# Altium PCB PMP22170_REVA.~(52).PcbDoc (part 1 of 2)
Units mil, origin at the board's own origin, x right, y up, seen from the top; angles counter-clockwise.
Board outline 4950 x 3450 mil, 2 copper layers (Top Layer, Bottom Layer), stack 62 mil thick; 75 components, 28 nets, 160 pads, 117 vias.
Unrouted connection lines stored in the file: 141.
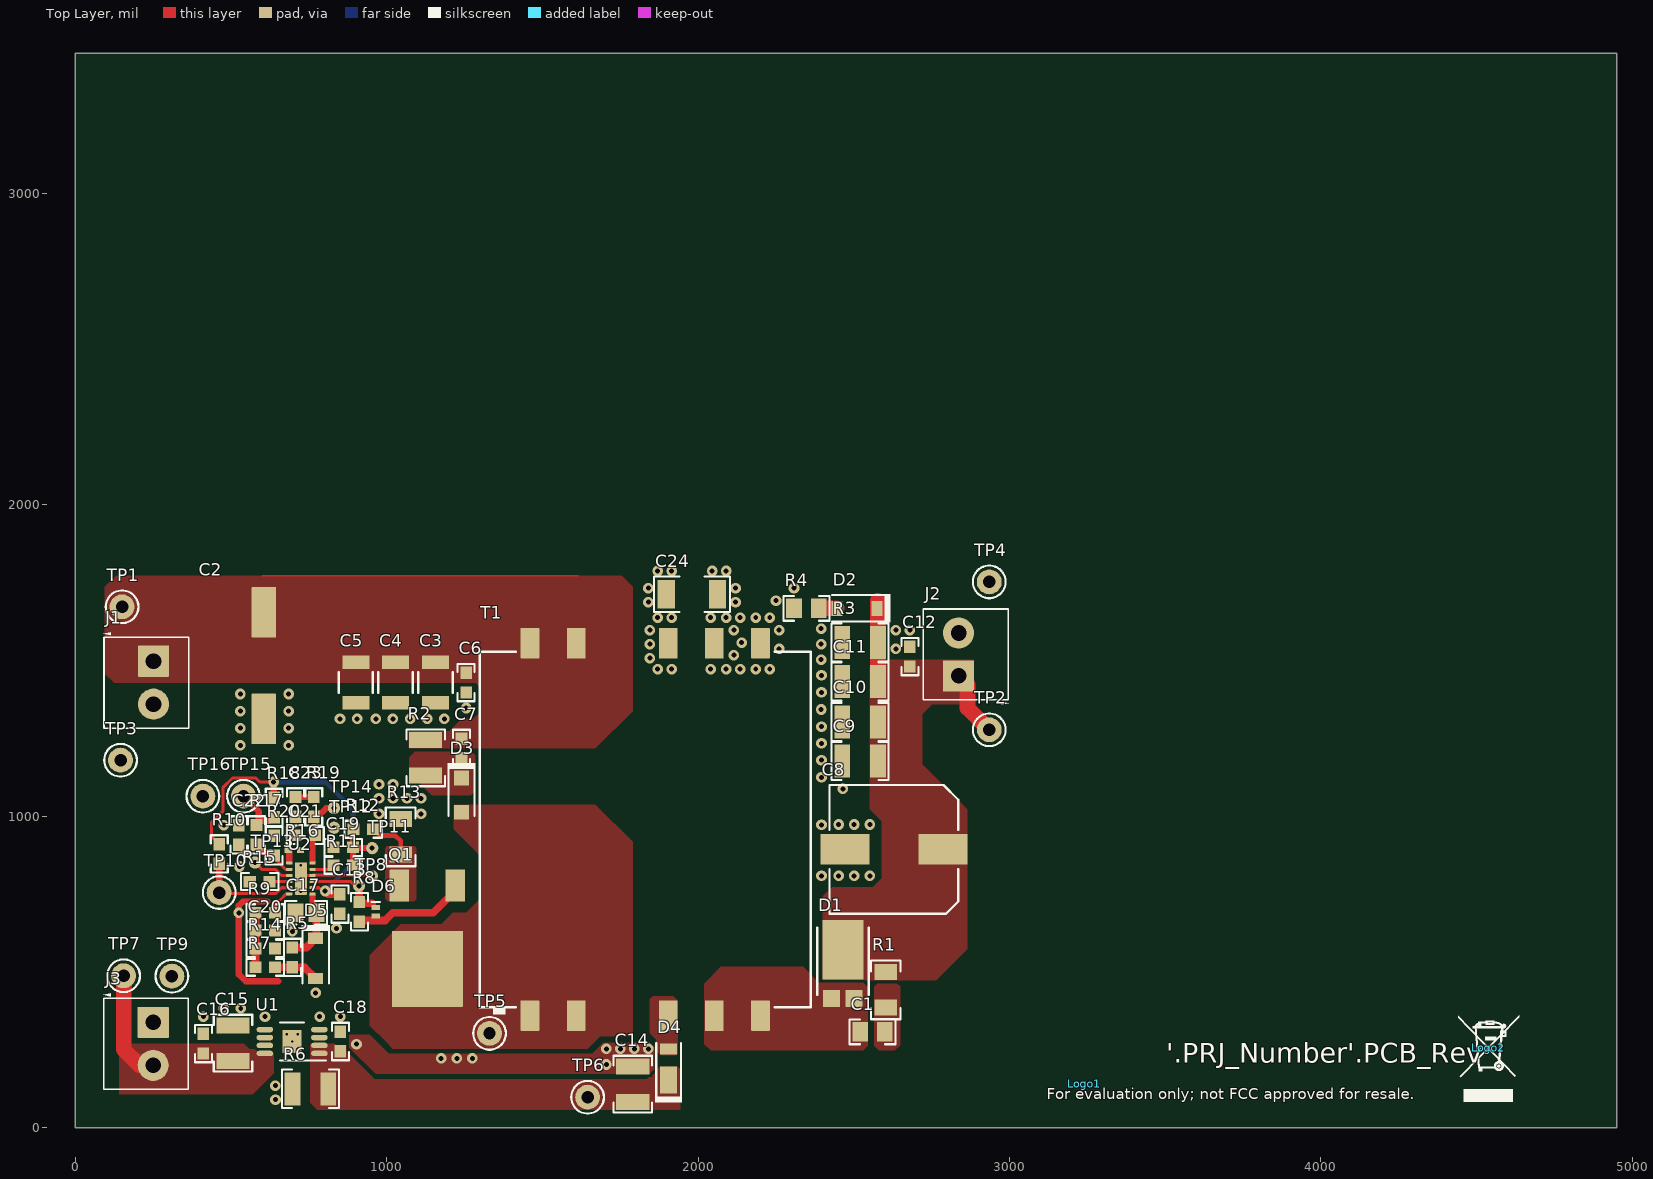
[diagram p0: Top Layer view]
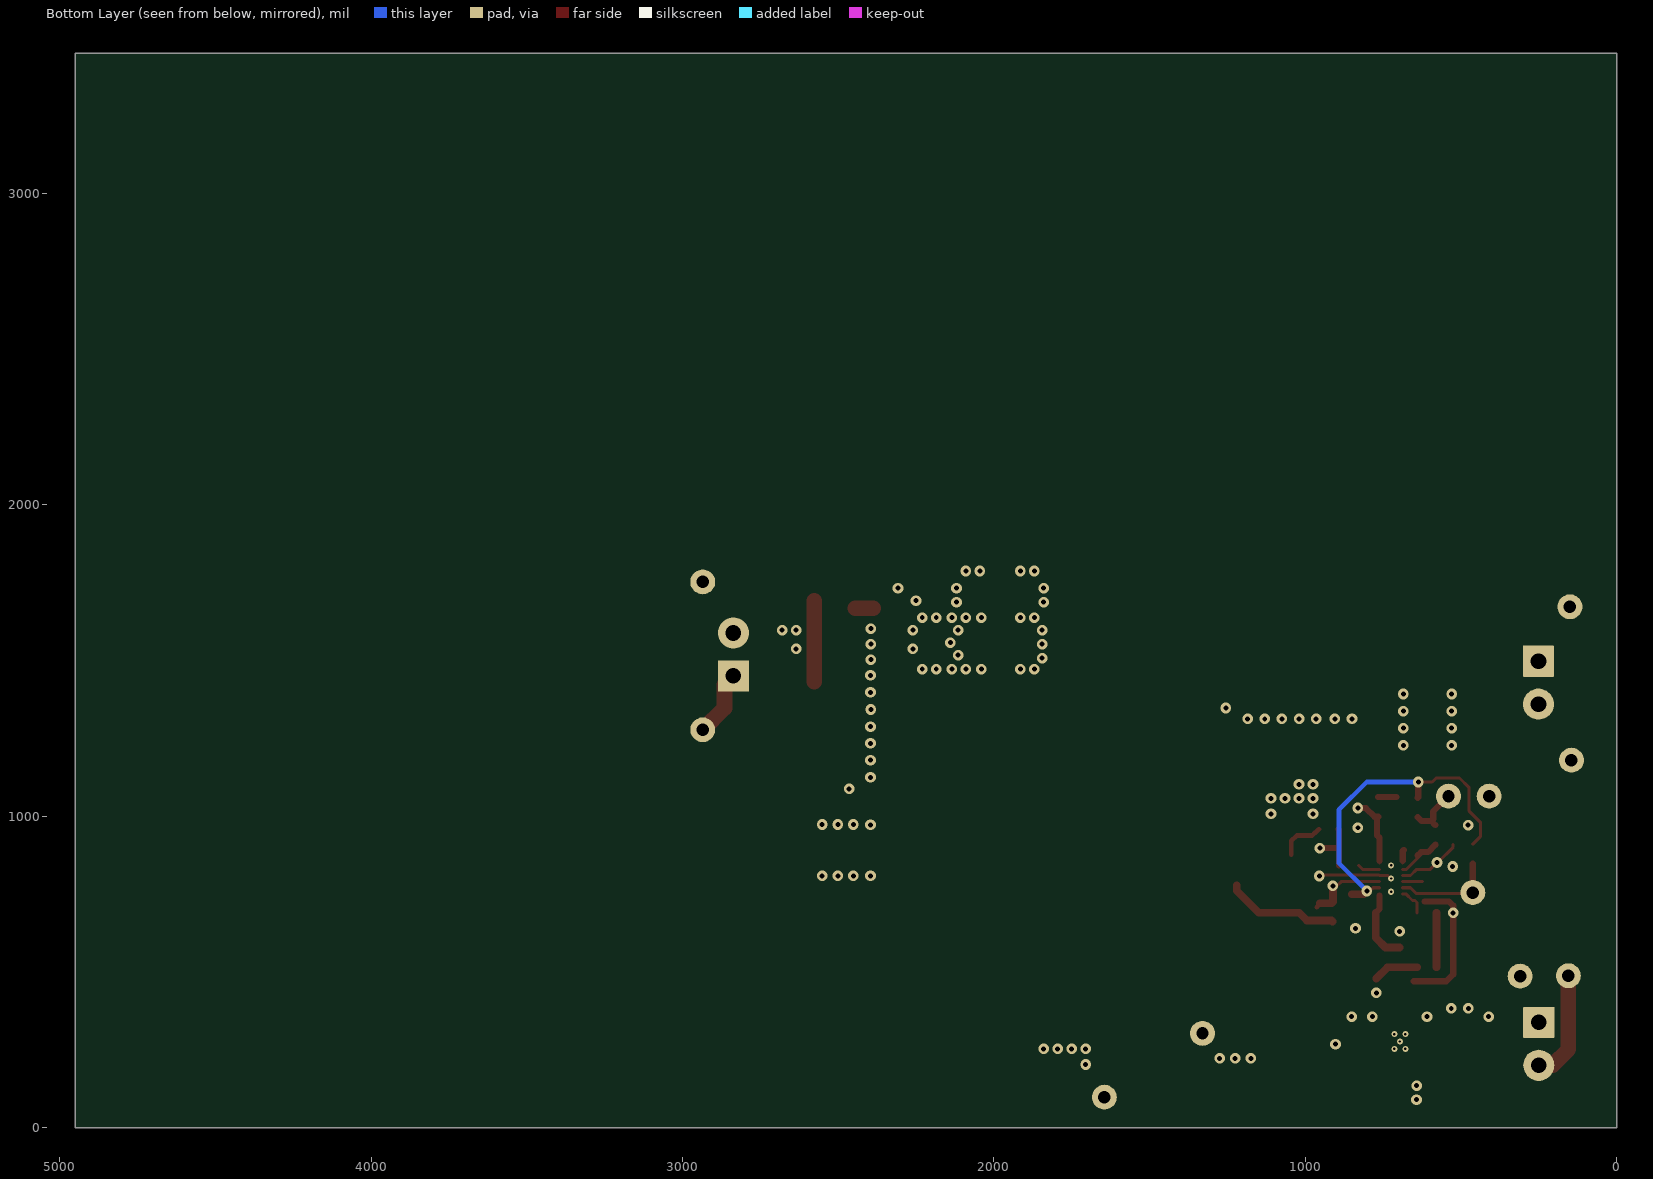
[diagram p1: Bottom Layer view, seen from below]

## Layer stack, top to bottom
Top Solder: solder mask 0.4, Solder Resist, Dk 3.5
Top Layer: signal copper 1.4
Dielectric1: core 59.2, FR-4, Dk 4.8
Bottom Layer: signal copper 1.4
Bottom Solder: solder mask 0.4, Solder Resist, Dk 3.5

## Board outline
0,0 4950,0 4950,3450 0,3450

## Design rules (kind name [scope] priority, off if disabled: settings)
AcuteAngle [All] p1: minimum=4.50000000000000E+0001 checktracksonly=FALSE
AssemblyTestPointUsage [All] p1: valid=2
BoardOutlineClearance BoardOutlineClearance_MountingHoles [OnCopper and InComponentClass('Mounting Holes')] p1: gap=39.37 ignorepadtopadclearanceinfootprint=FALSE
BoardOutlineClearance BoardOutlineClearance_Poly [OnCopper and IsPoly] p2: gap=25 ignorepadtopadclearanceinfootprint=FALSE
BoardOutlineClearance [OnCopper and Not InComponentClass('Logo') and not InComponentClass('FiducialMark') and not InRegion(1000,500,4000,800) and not InPoly] p3: gap=50 ignorepadtopadclearanceinfootprint=FALSE
Clearance Clearance_Keepouts [((IsTrack Or IsArc) And Not InPoly) And IsFree and IsKeepOut vs ((IsTrack Or IsArc) And Not InPoly) And IsFree and IsKeepOut] p1: gap=0 ignorepadtopadclearanceinfootprint=FALSE
Clearance Clearance_Poly [InPolygon] p2: gap=10 ignorepadtopadclearanceinfootprint=TRUE
Clearance Clearance_FiducialMark [IsKeepOut and InComponentClass('FiducialMark') vs IsPad and InComponentClass('FiducialMark')] p3: gap=0 ignorepadtopadclearanceinfootprint=FALSE
Clearance [All] p4: gap=7.87 ignorepadtopadclearanceinfootprint=TRUE
ComponentClearance ComponentClearance_MountingHoles_FiducialMarks [InComponentClass('Mounting Holes') vs InComponentClass('FiducialMark')] p1: gap=50 collisioncheckmode=3 verticalgap=10 showdistances=FALSE
ComponentClearance ComponentClearance_Shunt [InComponentClass('Header') vs InComponentClass('Shunt')] p2: gap=0 collisioncheckmode=3 verticalgap=0 showdistances=FALSE
ComponentClearance ComponentClearance_Logo [InComponentClass('Logo')] p3: gap=50 collisioncheckmode=3 verticalgap=10 showdistances=FALSE
ComponentClearance ComponentClearance_ScrewToNut [(HasFootprint('NY PMS 440 0025 PH')) vs (HasFootprint('Keystone_1902C'))] p4: gap=5 collisioncheckmode=3 verticalgap=10 showdistances=FALSE
ComponentClearance ComponentClearance_MountingHoles [InComponentClass('Mounting Holes')] p5: gap=250 collisioncheckmode=3 verticalgap=100000 showdistances=FALSE
ComponentClearance ComponentClearance_SmallPassives [HasFootprint('0201*') or HasFootprint('0402*') or HasFootprint('0508') or HasFootprint('0603*') or HasFootprint('0612') or HasFootprint('0805*') or HasFootprint('0815*') or HasFootprint('0830*') or HasFootprint('1206*') or HasFootprint('1210*') or HasFootprint('1808*') or HasFootprint('1812*') or HasFootprint('1825*') or HasFootprint('2010*') or HasFootprint('2220*') or HasFootprint('2225*') or HasFootprint('2512*') or HasFootprint('2728*') or HasFootprint('3518*') vs HasFootprint('0201*') or HasFootprint('0402*') or HasFootprint('0508') or HasFootprint('0603*') or HasFootprint('0612') or HasFootprint('0805*') or HasFootprint('0815*') or HasFootprint('0830*') or HasFootprint('1206*') or HasFootprint('1210*') or HasFootprint('1808*') or HasFootprint('1812*') or HasFootprint('1825*') or HasFootprint('2010*') or HasFootprint('2220*') or HasFootprint('2225*') or HasFootprint('2512*') or HasFootprint('2728*') or HasFootprint('3518*')] p6: gap=14.96 collisioncheckmode=3 verticalgap=10 showdistances=FALSE
ComponentClearance ComponentClearance_THtoSMT [IsThruComponent vs IsSMTComponent] p7: gap=30 collisioncheckmode=3 verticalgap=30 showdistances=FALSE
ComponentClearance ComponentClearance_THtoTH [IsThruComponent vs IsThruComponent] p8: gap=30 collisioncheckmode=3 verticalgap=30 showdistances=FALSE
ComponentClearance [All] p9: gap=20 collisioncheckmode=3 verticalgap=10 showdistances=FALSE
DiffPairsRouting [All] p1: maxlimit=100 minlimit=10 mostfreqgap=10 toplayer_minwidth=15 toplayer_maxwidth=15 toplayer_prefwidth=15 bottomlayer_minwidth=15 bottomlayer_maxwidth=15 bottomlayer_prefwidth=15 maxuncoupledlength=1000
FabricationTestPointUsage TestPointUsage [All] p1: valid=2 allowmultiple=FALSE
FabricationTestpoint Testpoint [All] p1: side=3 testpointundercomponent=TRUE minsize=40 maxsize=100 preferedsize=60 minholesize=0 maxholesize=40 preferedholesize=32 testpointgrid=1 allowsidetop=TRUE allowsidebottom=TRUE usegrid=TRUE gridtolerance=0.01
FanoutControl Fanout_LCC [IsLCC] p1: bgadir=Out bgaviamode=Centered fanoutstyle=Auto fanoutdirection=Alternating viagrid=1 // Fanout_LCC (Default Rule)
FanoutControl Fanout_BGA [IsBGA] p2: bgadir=Out bgaviamode=Centered fanoutstyle=Auto fanoutdirection=Alternating viagrid=1 // Fanout_BGA (Default Rule)
FanoutControl Fanout_Default [All] p4: bgadir=Out bgaviamode=Centered fanoutstyle=Auto fanoutdirection=Alternating viagrid=1 // Fanout_Default (Default Rule)
FanoutControl Fanout_Small [(CompPinCount < 5)] p5: bgadir=Out bgaviamode=Centered fanoutstyle=Auto fanoutdirection=OutThenIn viagrid=1 // Fanout_Small (Default Rule)
HoleSize [All] p1: absolutevalues=TRUE maxlimit=251 minlimit=7.87 maxpercent=80.000 minpercent=20.000
MinimumAnnularRing MinimumAnnularRing_ThermalPadVias [IsVia and InAnyComponent] p1: minimumring=5.91
MinimumAnnularRing [All] p2: minimumring=7.87
MinimumSolderMaskSliver MinimumSolderMaskSliver_Logo [InComponentClass('Logo') vs InComponentClass('Logo')] p1: minsoldermaskwidth=0.7
MinimumSolderMaskSliver [All] p2: minsoldermaskwidth=3.94
PlaneClearance [All] p1: clearance=15
PlaneConnect [All] p1: planeconnectstyle=Direct reliefexpansion=10 reliefentries=4 reliefconductorwidth=10 reliefairgap=10
PolygonConnect [All] p1: connectstyle=Direct reliefconductorwidth=10 reliefentries=4 polygonreliefangle="90 Angle" airgapwidth=10
RoutingVias ThermalPadVias [IsVia and InAnyComponent] p1: holewidth=7.87 width=19.68 viastyle="Through Hole" minholewidth=7.87 minwidth=19.68 maxholewidth=12.99 maxwidth=23.62
RoutingVias [All] p2: holewidth=16 width=34 viastyle="Through Hole" minholewidth=7.87 minwidth=26 maxholewidth=40 maxwidth=65
SilkToBoardRegionClearance [Not ((IsComment or IsDesignator) And (Hide <> 'False')) and not InRegion(1000,500,4000,800)] p1:
SilkToSilkClearance SilkToSilkClearance_Pb-FreeLogo [(HasFootprint('Pb-Free_Overlay_Medium') OR HasFootprint('Pb-Free_Overlay_Small')) vs (HasFootprint('Pb-Free_Overlay_Medium') OR HasFootprint('Pb-Free_Overlay_Small'))] p1: silktosilkclearance=0
SilkToSilkClearance [All] p2: silktosilkclearance=0
SilkToSolderMaskClearance SilkToComponentPadClearance [(IsPad or IsFill or IsRegion) and InAnycomponent] p1: minsilkscreentomaskgap=5 clearancetoexposedcopper=TRUE
SilkToSolderMaskClearance "Silk to Solder Mask Opening" [All] p2: minsilkscreentomaskgap=0 clearancetoexposedcopper=FALSE
SolderMaskExpansion [All] p1: expansion=1.97
UnRoutedNet [All] p1: checkbadconnections=TRUE
Width [All] p1: maxlimit=100 minlimit=6 preferedwidth=10 checkconnectedcopper=TRUE
13 further rules are at their usual default settings.

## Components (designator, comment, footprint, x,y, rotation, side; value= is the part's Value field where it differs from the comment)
C1 "Capacitor" 0805_HV 2560.14,307.59 r180 top value=100pF
C2 "EEH-ZS1H221V" FP-EEHZS1H221P_RADIAL_SMD-MFG 605.38,1483.94 r90 top
C3 "UMK325AB7106KMHT" 1210_280 1156.56,1428.94 r270 top value=10uF
C4 "UMK325AB7106KMHT" 1210_280 1028.6,1428.94 r270 top value=10uF
C5 "UMK325AB7106KMHT" 1210_280 900.65,1428.94 r270 top value=10uF
C6 "Capacitor" 0603 1254.98,1428.94 r270 top value=0.1uF
C7 "Capacitor" 0603 1240.14,1217.59 r270 top value=0.1uF
C8 "EEHZC1E331P" SM_RADIAL_10BMM 2628.67,893.44 r180 top value=330uF
C9 "TMK325B7226KMHT" 1210_270 2520.14,1177.59 r180 top value=22uF
C10 "TMK325B7226KMHT" 1210_270 2520.14,1302.59 r180 top value=22uF
C11 "TMK325B7226KMHT" 1210_270 2520.14,1432.59 r180 top value=22uF
C12 "Capacitor" 0603 2680.14,1512.59 r90 top value=0.1uF
C13 "GCM188R71E105KA64D" 0603 849.59,717.96 r270 top value=1uF
C14 "Capacitor" 1210_270 1790.14,139.68 r90 top value=22uF
C15 "Capacitor" 1210_270 506.18,271.05 r90 top value=47uF
C16 "Capacitor" 0603 411.18,269.79 r90 top value=0.1uF
C17 "Capacitor" 0805 740.44,689.89 r180 top value=1uF
C18 "Capacitor" 0603 851.18,276.48 r90 top value=0.1uF
C19 "Capacitor" 0603 860.36,899.93 r180 top value=1000pF
C20 "Capacitor" 0603 609.93,632.93 r0 top value=10pF
C21 "CGA3E2X7R2A222K080AA" 0603 737.98,938.43 r180 top value=2200pF
C22 "Capacitor" 0603 525.05,939.81 r90 top value=0.1uF
C23 "CGA3E3X7R1H334K080AB" 0603 706.97,1029.93 r270 top value=0.33uF
C24 "Capacitor" 1808 1980.14,1712.59 r180 top value=1000pF
D1 "PDS4200HQ-13" POWERDI5 2465.14,492.59 r90 top value=200V
D2 "MMSZ5240B-7-F" SOD-123 2510.31,1667.59 r180 top value=10V
D3 "DIODE_SCHOTTKY" SOD-123W 1240.14,1067.59 r270 top value=100V
D4 "DFLS1200Q-7" PowerDI123 1905.14,202.59 r90 top value=200V
D5 "SD103AW-7-F" SOD-123 771.97,543.43 r270 top value=40V
D6 "DIODE_SCHOTTKY" X1-DFN1006-2 964.51,692.96 r270 top value=30V
J1 "Receptacle_2x1" TERM_BLK_ED555-2DS 251.05,1497.83 r270 top
J2 "Receptacle_2x1" TERM_BLK_ED555-2DS 2836.64,1450.48 r90 top
J3 "Receptacle_2x1" TERM_BLK_ED555-2DS 250,338 r270 top
Logo1 "FCC disclaimer" FCC_disclaimer 3240,140 r0 top
Logo2 "WEEE logo" WEEE_Minimum 4537.4,255.91 r0 top
Q1 "IPD60N10S4L12ATMA1" DPAK 1130.49,643.71 r270 top value=100V
R1 "CRCW1206100RFKEAHP" 1206 2602.66,442.59 r90 top value=100
R2 "ERJ14NF1001U" 1210 1125.14,1187.59 r90 top value=1.00k
R3 "ERJ14NF1001U" 1210 2520.14,1557.59 r0 top value=1.00k
R4 "CRCW080580R6FKEA" 0805_HV 2347.91,1667.59 r0 top value=80.6
R5 "Resistor" 0603 696.97,546.74 r270 top value=0
R6 "ERJ14NF1001U" 1210 755.14,124.42 r0 top value=1.00k
R7 "CRCW0603100KFKEA" 0603 609.93,514.89 r0 top value=100k
R8 "Resistor" 0603 912.27,692.96 r90 top value=10.0
R9 "CRCW060371K5FKEA" 0603 609.93,689.93 r0 top value=71.5k
R10 "CRCW060310K0FKEA" 0603 461.97,878.78 r270 top value=10.0k
R11 "Resistor" 0603 860.36,842.25 r0 top value=0
R12 "Resistor" 0603 924.59,957.96 r0 top value=100
R13 "ERJ-8BWFR010V" 1206 1044.59,933.77 r270 top value=0.010
R14 "CRCW060324K9FKEA" 0603 609.93,574.93 r180 top value=24.9k
R15 "CRCW060373K2FKEA" 0603 591.97,790.08 r0 top value=73.2k
R16 "CRCW04020000Z0ED" 0402L 703.53,891.58 r180 top value=0
R17 "Resistor" 0603 581.97,939.93 r270 top value=6.04k
R18 "CRCW060320R0FKEA" 0603 638.47,1027.98 r90 top value=20.0
R19 "CRCW06033K01FKEA" 0603 765.48,1029.93 r270 top value=3.01k
R20 "CRCW06031K00FKEA" 0603 638.47,905.36 r270 top value=1.00k
T1 "750315862" Wurth_750315862 1830.14,957.59 r90 top value=45uH
TP1 "5000" Keystone5000 150.14,1672.59 r90 top
TP2 "5000" Keystone5000 2935.14,1277.59 r90 top
TP3 "5001" Keystone5001 145.14,1179.91 r90 top
TP4 "5001" Keystone5001 2935.06,1752.59 r90 top
TP5 "5002" Keystone5002 1330.14,302.59 r0 top
TP6 "5000" Keystone5000 1645.14,97.59 r270 top
TP7 "5000" Keystone5000 155,487.6 r270 top
TP8 "TP_SM_1MM" TP_SM_1MM 911.11,776.5 r90 top
TP9 "5001" Keystone5001 310,486.34 r270 top
TP10 "5000" Keystone5000 461.97,754.93 r0 top
TP11 "TP_SM_1MM" TP_SM_1MM 953.43,897.49 r270 top
TP12 "TP_SM_1MM" TP_SM_1MM 830.89,962.96 r270 top
TP13 "TP_SM_1MM" TP_SM_1MM 576.97,851.23 r0 top
TP14 "TP_SM_1MM" TP_SM_1MM 830.89,1026.29 r0 top
TP15 "5003" Keystone5003 540.04,1064.38 r0 top
TP16 "5001" Keystone5001 409.59,1064.38 r0 top
U1 "TPS7B8250QDGNRQ1" DGN0008D_N 696.18,276.48 r180 top
U2 "LM5155QDSSTQ1" DSS0012C 724.57,799.93 r180 top

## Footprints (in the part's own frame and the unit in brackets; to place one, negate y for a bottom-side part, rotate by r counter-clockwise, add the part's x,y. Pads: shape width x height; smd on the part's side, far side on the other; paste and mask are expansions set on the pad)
0402L [mm] "0402 from SM-752 data"
  rect 0.6x0.5 smd: 1(-0.5,0) 2(0.5,0)
  body extent -0.55,-0.3 0.55,0.3, height 0.6
0603 [mm] "0603 from SM-752 data"
  rect 1x0.95 smd: 1(-0.8,0) 2(0.8,0)
  silkscreen extent -1.52,-0.69 1.52,0.69, body extent -0.87,-0.47 0.87,0.47, height 1
0805 [mm] "0805 from SM-752 data"
  rect 1.3x1.5 smd: 1(-0.85,0) 2(0.85,0)
  silkscreen extent -1.72,-0.97 1.72,0.97, body extent -1.1,-0.72 1.1,0.72, height 1.45
0805_HV [mil] "0805 with 30mil clearance between pads"
  rect 50x63 smd: 1(-40,0) 2(40,0)
  silkscreen extent -74,-40 74,40, body extent -43,-29 43,29, height 57
1206 [mm] "1206 from SM-752 data"
  rect 1.3x1.85 smd: 1(-1.45,0) 2(1.45,0)
  silkscreen extent -2.4,-1.21 2.4,1.21, body extent -1.7,-0.9 1.7,0.9, height 1.35
1210 [mm] "1210 from SM-752 data"
  rect 1.3x2.7 smd: 1(-1.45,0) 2(1.45,0)
  silkscreen extent -2.32,-1.57 2.32,1.57, body extent -1.7,-1.35 1.7,1.35, height 1.35
1210_270 [mm] "1210"
  rect 1.3x2.7 smd: 1(-1.45,0) 2(1.45,0)
  silkscreen extent -2.32,-1.57 2.32,1.57, body extent -1.7,-1.35 1.7,1.35, height 2.7
1210_280 [mm] "SMD, 2-Leads, Body 3.6x2.8mm, Height 2.8mm"
  rect 1.1x2.2 smd: 1(-1.65,0) 2(1.65,0)
  silkscreen extent -0.84,-1.4 0.84,1.4, body extent -1.8,-1.4 1.8,1.4, height 2.8
1808 [mm] "Chip Capacitor, Body 4.6x2.0mm, IPC Medium Density"
  rect 1.4x2.3 smd: 1(-2.1,0) 2(2.1,0)
  silkscreen extent -3.1,-1.45 3.1,1.45, body extent -2.47,-1.2 2.47,1.2, height 2.03
DGN0008D_N [mm] "TSOP, 8-Leads, Body 3x3mm, Pitch 0.65mm, Thermal Pad 1.89x1.57mm, IPC Medium Density"
  rrect100% 1.35x0.45 smd: 1(-2.225,0.975) 2(-2.225,0.325) 3(-2.225,-0.325) 4(-2.225,-0.975) 5(2.225,-0.975) 6(2.225,-0.325) 7(2.225,0.325) 8(2.225,0.975)
  rrect6% 1.57x1.89 smd: 9(0,0)
  silkscreen extent -2.73,-1.55 0.95,1.55, body extent -2.46,-1.5 2.46,1.5, height 1.1
DPAK [mm] "D-PAK, 3-Pads, Body 6.22x6.73mm (max), TO-252AA using nominal STEP model"
  rrect6% 2.6x1.6 smd: 1(-3.4,2.28) 3(-3.4,-2.28)
  rrect2% 6.2x5.8 smd paste-3: 2(3.4,0)
  body extent -3.86,-3.29 5.84,3.29, height 2.48
DSS0012C [mm] "WSON-12"
  rrect40% 0.5x0.25 smd: 1(-0.95,1.25) 2(-0.95,0.75) 3(-0.95,0.25) 4(-0.95,-0.25) 5(-0.95,-0.75) 6(-0.95,-1.25) 7(0.95,-1.25) 8(0.95,-0.75) 9(0.95,-0.25) 10(0.95,0.25) 11(0.95,0.75) 12(0.95,1.25)
  rrect11% 0.95x1.17 on Top Paste: 13(0,0.685) 13(0,-0.685)
  rrect11% 1x2.65 smd paste-0.5: 13(0,0)
  body extent -1,-1.5 1,1.5, height 0.81
FCC_disclaimer [mil]
FP-EEHZS1H221P_RADIAL_SMD-MFG [mm]
  rrect5% 4.1x2 smd paste+0 mask+0: 1(-4.35,0) 2(4.35,0)
  body extent -6.65,-5.5 6.65,5.5, height 0.25
Keystone5000 [mil] "For Keystone 500x miniature loop terminals"
  round 80 hole 40: 1(0,0)
  silkscreen extent -52,-52 52,52, body extent -49,-49 49,49, height 182
Keystone5001 [mil] "For Keystone 500x miniature loop terminals"
  round 80 hole 40: 1(0,0)
  silkscreen extent -52,-52 52,52, body extent -49,-49 49,49, height 182
Keystone5002 [mil] "For Keystone 500x miniature loop terminals"
  round 80 hole 40: 1(0,0)
  silkscreen extent -52,-52 52,52, body extent -49,-49 49,49, height 182
Keystone5003 [mil] "For Keystone 500x miniature loop terminals"
  round 80 hole 40: 1(0,0)
  silkscreen extent -52,-52 52,52, body extent -49,-49 49,49, height 182
POWERDI5 [mm] "Diodes Inc recommended land pattern, ap02001.pdf rev 60"
  rect 1.4x1.39 smd: 1(-1.991,0.92) 2(-1.991,-0.92)
  rect 4.86x3.36 smd: 3(1.991,0)
  silkscreen extent -1.7,-2.1 3.8,2.1, body extent -2.27,-2.03 4.33,2.03, height 1.17
PowerDI123 [mm] "Diodes Inc recommended land pattern, document number DS30628 Rev. 6-2"
  rect 2.2x1.4 smd: 1(-1.275,0)
  rect 0.9x1.4 smd: 2(1.275,0)
  silkscreen extent -3.1,-1.09 1.76,1.09, body extent -2.38,-0.97 1.52,0.96, height 1
SM_RADIAL_10BMM [mm] "Nichicon 10x10"
  rect 4x2.5 smd: 1(-4,0) 2(4,0)
  silkscreen extent -5.25,-5.25 5.25,5.25, body extent -5.25,-5.25 5.25,5.25, height 10.5
SOD-123 [mm] "On Semi recommended land pattern"
  rect 0.915x1.22 smd: 1(-1.637,0) 2(1.637,0)
  silkscreen extent -2.74,-1.17 2.03,1.17, body extent -1.93,-0.9 1.93,0.9, height 1.35
SOD-123W [mm] "NXP recommended land pattern"
  rect 1.2x1.2 smd paste-0.05: 1(-1.4,0) 2(1.4,0)
  silkscreen extent -2.64,-1.14 1.68,1.14, body extent -1.85,-0.95 1.85,0.95, height 1.1
TERM_BLK_ED555-2DS [mil]
  rrect4% 100x100 hole 50: 1(0,0)
  round 100 hole 50: 2(138,0)
  silkscreen extent -93,-161 215,113, body extent -69,-150 207,106, height 323
TP_SM_1MM [mm] "1mm Test Point, SMT"
  round 1 smd paste-0.5: 1(0,0)
WEEE_Minimum [mil] "WEEElie bin"
  silkscreen extent -95,-172 99,104
Wurth_750315862 [mm] "SMD, 12-Leads, Body 32.45x27.03mm, Pitch 3.76mm"
  rrect7% 2.5x1.52 smd: 1(-15.19,9.4) 2(-15.19,5.64) 4(-15.19,-1.88) 5(-15.19,-5.64) 6(-15.19,-9.4) 7(15.19,-9.4) 8(15.19,-5.64) 9(15.19,-1.88) 11(15.19,5.64) 12(15.19,9.4)
  silkscreen extent -15.1,-13.51 14.5,13.51, body extent -16.25,-13.51 16.25,13.51, height 13.98
X1-DFN1006-2 [mm] "DIODES, INC"
  rect 0.4x0.7 smd: 1(-0.35,0) 2(0.35,0)
  silkscreen extent -0.8,-0.35 -0.8,0.35, body extent -0.54,-0.34 0.54,0.34, height 0.53

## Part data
C1: library part CMP-0008236-2, "CAP, CERM, 100 pF, 250 V, +/- 5%, C0G/NP0, 0805", Cap_Case=0805, Manufacturer=MuRata, PartNumber=GRM21A5C2E101JW01D, Supplier Part Number 1=490-5542-1-ND, TempCo=C0G/NP0, Tolerance_%=5%, Value1=Unknown, Value2=250V, ValueDisplayed=100pF
C2: library part CMP-0087071-1, "220µF 50V Aluminum Polymer Capacitor Radial, Can - SMD 13 mOhm 4000 Hrs @ 125°C", Manufacturer=Panasonic, Tolerance_%=20%
C3 C4 C5: library part CMP-0009258-2, "CAP, CERM, 10 uF, 50 V, +/- 10%, X7R, AEC-Q200 Grade 1, 1210", Cap_Case=1210, Manufacturer="Taiyo Yuden", Supplier Part Number 1=587-4326-1-ND, TempCo=X7R, Tolerance_%=10%, Value1=Unknown, Value2=50V, ValueDisplayed=10uF
C6 C7 C12: library part CMP-0007144-4, "CAP, CERM, 0.1 uF, 50 V, +/- 10%, X7R, 0603", Cap_Case=0603, Manufacturer=MuRata, PartNumber=GCM188R71H104KA57D, Supplier Part Number 1=490-4779-1-ND, TempCo=X7R, Tolerance_%=10%, Value1="0.02 ohm", Value2=50V, ValueDisplayed=0.1uF
C8: library part CMP-0012593-3, "CAP, Polymer Hybrid, 330 uF, 25 V, +/- 20%, 20 mohm, 10x10 SMD", Manufacturer=Panasonic, Supplier Part Number 1=P15459CT-ND, Tolerance_%=20%, Value1="20 ohm", Value2=25V, ValueDisplayed=330uF
C9 C10 C11: library part CMP-0009255-2, "CAP, CERM, 22 uF, 25 V, +/- 10%, X7R, AEC-Q200 Grade 1, 1210", Cap_Case=1210, Manufacturer="Taiyo Yuden", Supplier Part Number 1=587-4337-1-ND, TempCo=X7R, Tolerance_%=10%, Value1=Unknown, Value2=25V, ValueDisplayed=22uF
C13: library part CMP-0007139-4, "CAP, CERM, 1 uF, 25 V, +/- 10%, X7R, AEC-Q200 Grade 1, 0603", Cap_Case=0603, Manufacturer=MuRata, Supplier Part Number 1=490-10673-1-ND, TempCo=X7R, Tolerance_%=10%, Value1=Unknown, Value2=25V, ValueDisplayed=1uF
C14: library part CMP-0009224-2, "CAP, CERM, 22 uF, 25 V, +/- 10%, X7R, 1210", Cap_Case=1210, Manufacturer=MuRata, PartNumber=GRM32ER71E226KE15L, Supplier Part Number 1=490-5313-1-ND, TempCo=X7R, Tolerance_%=10%, Value1=Unknown, Value2=25V, ValueDisplayed=22uF
C15: library part CMP-0009220-2, "CAP, CERM, 47 uF, 10 V, +/- 10%, X7R, 1210", Cap_Case=1210, Manufacturer=MuRata, PartNumber=GRM32ER71A476KE15L, Supplier Part Number 1=490-5312-1-ND, TempCo=X7R, Tolerance_%=10%, Value1=Unknown, Value2=10V, ValueDisplayed=47uF
C16 C18 C22: library part CMP-0007378-5, "CAP, CERM, 0.1 uF, 16 V, +/- 10%, X7R, 0603", Cap_Case=0603, Manufacturer=MuRata, PartNumber=GRM188R71C104KA01D, Supplier Part Number 1=490-1532-1-ND, TempCo=X7R, Tolerance_%=10%, Value1=Unknown, Value2=16V, ValueDisplayed=0.1uF
C17: library part CMP-0008350-2, "CAP, CERM, 1 uF, 50 V, +/- 10%, X7R, 0805", Cap_Case=0805, Manufacturer=MuRata, PartNumber=GRM21BR71H105KA12L, Supplier Part Number 1=490-4736-1-ND, TempCo=X7R, Tolerance_%=10%, Value1=Unknown, Value2=50V, ValueDisplayed=1uF
C19: library part CMP-0007402-4, "CAP, CERM, 1000 pF, 25 V, +/- 10%, X7R, 0603", Cap_Case=0603, Manufacturer=MuRata, PartNumber=GRM188R71E102KA01D, Supplier Part Number 1=GRM188R71E102KA01D-ND, TempCo=X7R, Tolerance_%=10%, Value1=Unknown, Value2=25V, ValueDisplayed=1000pF
C20: library part CMP-0007170-4, "CAP, CERM, 10 pF, 50 V, +/- 5%, C0G/NP0, 0603", Cap_Case=0603, Manufacturer=MuRata, PartNumber=GRM1885C1H100JA01D, Supplier Part Number 1=490-1403-1-ND, TempCo=C0G/NP0, Tolerance_%=5%, Value1=Unknown, Value2=50V, ValueDisplayed=10pF
C21: library part CMP-0007085-4, "CAP, CERM, 2200 pF, 100 V, +/- 10%, X7R, AEC-Q200 Grade 1, 0603", Cap_Case=0603, Manufacturer=TDK, Supplier Part Number 1=445-5808-1-ND, TempCo=X7R, Tolerance_%=10%, Value1="0.923948 ohm", Value2=100V, ValueDisplayed=2200pF
C23: library part CMP-0007095-4, "CAP, CERM, 0.33 uF, 50 V, +/- 10%, X7R, AEC-Q200 Grade 1, 0603", Cap_Case=0603, Manufacturer=TDK, Supplier Part Number 1=445-174426-1-ND, TempCo=X7R, Tolerance_%=10%, Value1="0.01584 ohm", Value2=50V, ValueDisplayed=0.33uF
C24: library part CMP-0009436-2, "CAP, CERM, 1000 pF, 2000 V, +/- 10%, X7R, 1808", Cap_Case=1808, Manufacturer=MuRata, PartNumber=GR442QR73D102KW01L, Supplier Part Number 1=490-8145-1-ND, TempCo=X7R, Tolerance_%=10%, Value1=Unknown, Value2=2000V, ValueDisplayed=1000pF
D1: library part CMP-0081019-2, "Diode, Schottky, 200 V, 4 A, AEC-Q101, PowerDI5", Manufacturer="Diodes Inc.", Value1=4A, Value2=0.84V
D2: library part CMP-0005749-3, "Diode, Zener, 10 V, 500 mW, SOD-123", Manufacturer="Diodes Inc.", Power_W=500mW, Value1=0.5W
D3: library part CMP-0028782-2, "Diode, Schottky, 100 V, 1 A, AEC-Q101, SOD-123W", Manufacturer=Nexperia, PartNumber=PMEG10010ELRX, Value1=1A, Value2=0.77V
D4: library part CMP-0028517-2, "Diode, Schottky, 200 V, 1 A, PowerDI123", Manufacturer="Diodes Inc.", Value1=1A, Value2=0.85V
D5: library part CMP-0028543-1, "Diode, Schottky, 40 V, 0.35 A, SOD-123", Manufacturer="Diodes Inc.", Supplier Part Number 1=SD103-AWDICT-ND, Value1=0.35A, Value2=0.55V
D6: library part CMP-0076931-2, "Diode, Schottky, 30 V, 0.2 A, 1.00x0.50x0.60mm", Manufacturer="Diodes Inc.", PartNumber=BAT54LP-7, Value1=0.2A, Value2=1V
J1 J2 J3: library part CMP-0074913-1, "Terminal Block, 3.5mm Pitch, 2x1, TH", Color=Grey, Current_A=6A, Manufacturer="On-Shore Technology", PartNumber=ED555/2DS, Supplier Part Number 1=ED1514-ND, Voltage_V=150V
Logo1: library part CMP-0074847-1, "FCC_disclaimer"
Logo2: library part CMP-0074769-1
Q1: library part CMP-0080670-2, "MOSFET, N-CH, 100 V, 60 A, AEC-Q101, DPAK", Alternate Manufacturer=None, Manufacturer="Infineon Technologies", Supplier Part Number 1=IPD60N10S4L12ATMA1CT-ND, Value1="0.015 ohm", Value2="38 nC"
R1: library part CMP-0016570-3, "RES, 100, 1%, 0.5 W, AEC-Q200 Grade 0, 1206", Manufacturer=Vishay-Dale, Power_W=500mW, Supplier Part Number 1=541-100UCT-ND, TempCo="100 ppm/C", Tolerance_%=1%, Value2=0.5W, Value_Code=100R, ValueDisplayed=100
R2 R3 R6: library part CMP-0015030-3, "RES, 1.00 k, 1%, 0.5 W, AEC-Q200 Grade 0, 1210", Manufacturer=Panasonic, Power_W=500mW, Supplier Part Number 1=P1.00KAACT-ND, TempCo="100 ppm/C", Tolerance_%=1%, Value2=0.5W, Value_Code=1k00, ValueDisplayed=1.00k
R4: library part CMP-0021452-3, "RES, 80.6, 1%, 0.125 W, AEC-Q200 Grade 0, 0805", Manufacturer=Vishay-Dale, Power_W=125mW, Supplier Part Number 1=541-80.6CCT-ND, TempCo="100 ppm/C", Tolerance_%=1%, Value2=0.125W, Value_Code=80R6, ValueDisplayed=80.6
R5 R11: library part CMP-0025697-4, "RES, 0, 5%, 0.1 W, AEC-Q200 Grade 0, 0603", Manufacturer=Vishay-Dale, PartNumber=CRCW06030000Z0EA, Power_W=100mW, Supplier Part Number 1=541-0.0GCT-ND, TempCo="200 ppm/C", Tolerance_%=5%, Value2=0.1W, Value_Code=0000, ValueDisplayed=0
R7: library part CMP-0021990-4, "RES, 100 k, 1%, 0.1 W, AEC-Q200 Grade 0, 0603", Manufacturer=Vishay-Dale, Power_W=100mW, Supplier Part Number 1=541-100KHCT-ND, TempCo="100 ppm/C", Tolerance_%=1%, Value2=0.1W, Value_Code=100k
R8: library part CMP-0022003-4, "RES, 10.0, 1%, 0.1 W, AEC-Q200 Grade 0, 0603", Manufacturer=Vishay-Dale, PartNumber=CRCW060310R0FKEA, Power_W=100mW, Supplier Part Number 1=541-10.0HCT-ND, TempCo="100 ppm/C", Tolerance_%=1%, Value2=0.1W, Value_Code=10R0, ValueDisplayed=10.0
R9: library part CMP-0022581-4, "RES, 71.5 k, 1%, 0.1 W, AEC-Q200 Grade 0, 0603", Manufacturer=Vishay-Dale, Power_W=100mW, Supplier Part Number 1=541-71.5KHCT-ND, TempCo="100 ppm/C", Tolerance_%=1%, Value2=0.1W, Value_Code=71k5, ValueDisplayed=71.5k
R10: library part CMP-0021998-4, "RES, 10.0 k, 1%, 0.1 W, AEC-Q200 Grade 0, 0603", Manufacturer=Vishay-Dale, Power_W=100mW, Supplier Part Number 1=541-10.0KHCT-ND, TempCo="100 ppm/C", Tolerance_%=1%, Value2=0.1W, Value_Code=10k0, ValueDisplayed=10.0k
R12: library part CMP-0021991-4, "RES, 100, 1%, 0.1 W, AEC-Q200 Grade 0, 0603", Manufacturer=Vishay-Dale, PartNumber=CRCW0603100RFKEA, Power_W=100mW, Supplier Part Number 1=541-100HCT-ND, TempCo="100 ppm/C", Tolerance_%=1%, Value2=0.1W, Value_Code=100R, ValueDisplayed=100
R13: library part CMP-0750151-1, "RES, 0.010, 1%, 1 W, AEC-Q200 Grade 0, 1206", Manufacturer=Panasonic, Power_W=1W, TempCo="200 ppm/C", Tolerance_%=1%, Value_Code=R010, ValueDisplayed=0.010
R14: library part CMP-0022237-4, "RES, 24.9 k, 1%, 0.1 W, AEC-Q200 Grade 0, 0603", Manufacturer=Vishay-Dale, Power_W=100mW, Supplier Part Number 1=541-24.9KHCT-ND, TempCo="100 ppm/C", Tolerance_%=1%, Value2=0.1W, Value_Code=24k9, ValueDisplayed=24.9k
R15: library part CMP-0022585-4, "RES, 73.2 k, 1%, 0.1 W, AEC-Q200 Grade 0, 0603", Manufacturer=Vishay-Dale, Power_W=100mW, Supplier Part Number 1=541-73.2KHCT-ND, TempCo="100 ppm/C", Tolerance_%=1%, Value2=0.1W, Value_Code=73k2, ValueDisplayed=73.2k
R16: library part CMP-0026822-3, "RES, 0, 5%, 0.063 W, AEC-Q200 Grade 0, 0402", Manufacturer=Vishay-Dale, Power_W=63mW, Supplier Part Number 1=541-0.0JCT-ND, TempCo="200 ppm/C", Tolerance_%=5%, Value2=0.063W, Value_Code=0000, ValueDisplayed=0
R17: library part CMP-0022558-4, "RES, 6.04 k, 1%, 0.1 W, AEC-Q200 Grade 0, 0603", Manufacturer=Vishay-Dale, PartNumber=CRCW06036K04FKEA, Power_W=100mW, Supplier Part Number 1=541-6.04KHCT-ND, TempCo="100 ppm/C", Tolerance_%=1%, Value2=0.1W, Value_Code=6k04, ValueDisplayed=6.04k
R18: library part CMP-0022206-4, "RES, 20.0, 1%, 0.1 W, AEC-Q200 Grade 0, 0603", Manufacturer=Vishay-Dale, Power_W=100mW, Supplier Part Number 1=541-20.0HCT-ND, TempCo="100 ppm/C", Tolerance_%=1%, Value2=0.1W, Value_Code=20R0, ValueDisplayed=20.0
R19: library part CMP-0022371-4, "RES, 3.01 k, 1%, 0.1 W, AEC-Q200 Grade 0, 0603", Manufacturer=Vishay-Dale, Power_W=100mW, Supplier Part Number 1=541-3.01KHCT-ND, TempCo="100 ppm/C", Tolerance_%=1%, Value2=0.1W, Value_Code=3k01, ValueDisplayed=3.01k
R20: library part CMP-0022109-5, "RES, 1.00 k, 1%, 0.1 W, AEC-Q200 Grade 0, 0603", Manufacturer=Vishay-Dale, Power_W=100mW, Supplier Part Number 1=541-1.00KHCT-ND, TempCo="100 ppm/C", Tolerance_%=1%, Value2=0.1W, Value_Code=1k00, ValueDisplayed=1.00k
T1: library part CMP-0030646-1, "Transformer, 45 uH, SMT", Manufacturer="Wurth Elektronik", ValueDisplayed=45uH
TP1 TP2 TP6 TP7 TP10: library part CMP-0055137-1, "Test Point, Miniature, Red, TH", Color=Red, Manufacturer=Keystone, Supplier Part Number 1=36-5000-ND
TP3 TP4 TP9 TP16: library part CMP-0055138-1, "Test Point, Miniature, Black, TH", Color=Black, Manufacturer=Keystone, Supplier Part Number 1=36-5001-ND
TP5: library part CMP-0055139-1, "Test Point, Miniature, White, TH", Color=White, Manufacturer=Keystone, Supplier Part Number 1=36-5002-ND
TP8 TP11 TP12 TP13 TP14: library part CMP-0003825-1, "1mm Test Point, SMT", Manufacturer=Any
TP15: library part CMP-0055140-1, "Test Point, Miniature, Orange, TH", Color=Orange, Manufacturer=Keystone, Supplier Part Number 1=36-5003-ND
U1: library part CMP-0013313-4, "300mA High-Voltage Ultra-Low-Iq Low-Dropout (LDO) Regulator, DGN0008D (VSSOP-8)", Alternate Manufacturer="Texas Instruments"
U2: library part CMP-0081538-1, "Automotive Grade 2.2-MHz Wide Input Non-synchronous Boost Controller, DSS0012C (WSON-12)", Alternate Manufacturer="Texas Instruments", Alternate PartNumber=LM5155QDSSRQ1

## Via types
v1: diameter 34, hole 16, Top Layer to Bottom Layer, 109 vias
v2: diameter 19.68, hole 7.87, Top Layer to Bottom Layer, 8 vias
